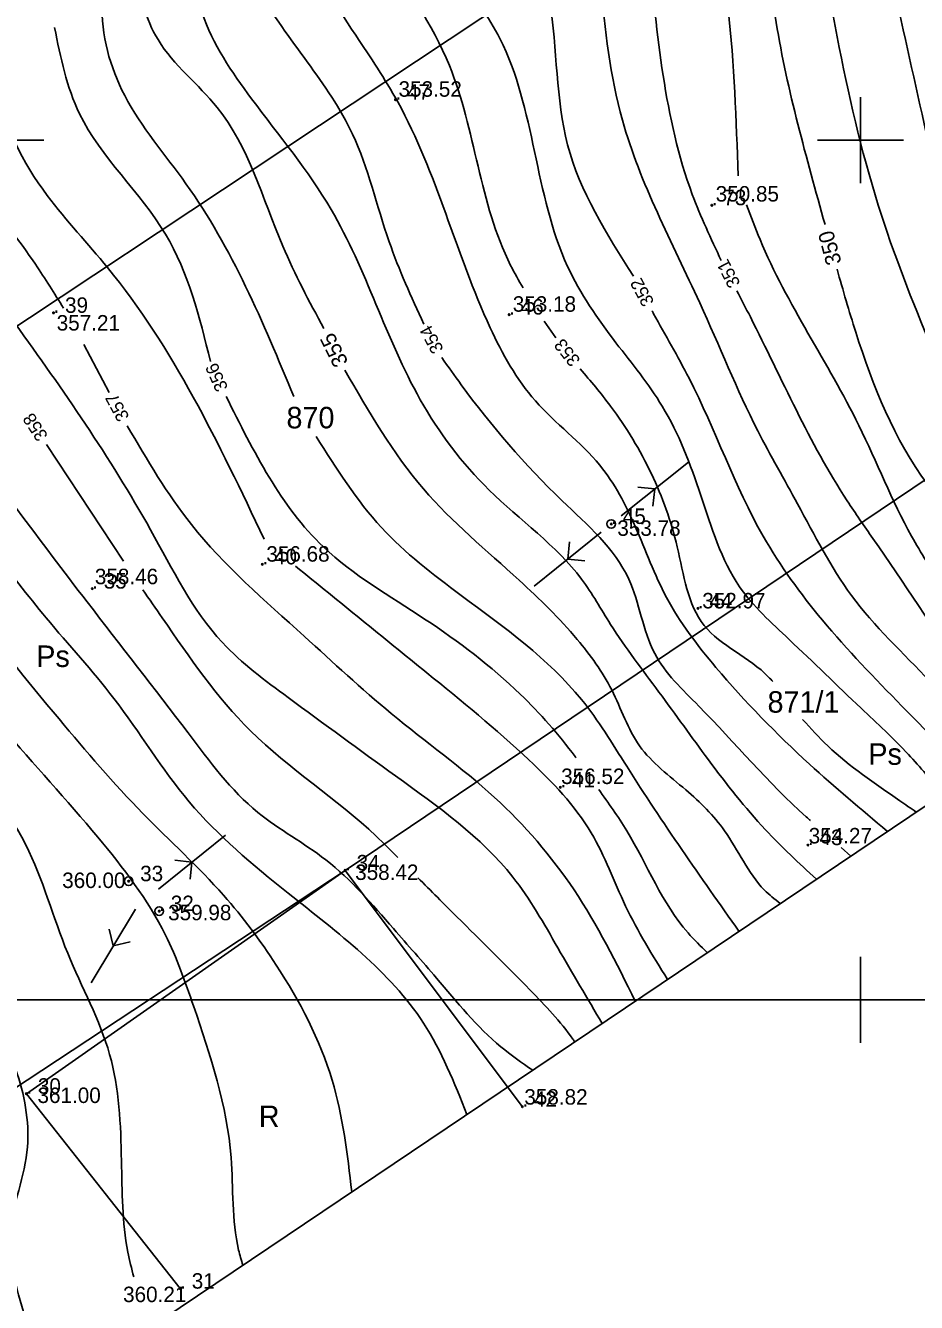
# Model space of a CAD drawing. Extents: x 4632591 to 4651936, y 5351032 to 5369988.
# Drawn here: x 4638451.4 to 4638503.3, y 5357982.4 to 5358056.7 of the extents above; entities that cross this region are included whole.
import ezdxf

# ---------------------------------------------------------------- set-up
doc = ezdxf.new("R2010")
doc.units = 0
for name, color, linetype in [('EDZPD_211', 7, 'Continuous'), ('EDZPD_219', 7, 'Continuous'), ('EKLPK_209', 7, 'Continuous'), ('EUZPU_218', 7, 'Continuous'), ('UEEPA_510', 7, 'Continuous'), ('UEETA_516', 7, 'Continuous'), ('Warstwa 40', 7, 'Continuous'), ('Warstwa 60', 7, 'Continuous'), ('Warstwa 62', 7, 'Continuous'), ('WUKPS_403', 7, 'Continuous'), ('WWRPH_811', 7, 'Continuous'), ('WWRPH_812', 7, 'Continuous'), ('WWRPH_814', 7, 'Continuous')]:
    doc.layers.add(name, color=color, linetype=linetype)

msp = doc.modelspace()

# ---------------------------------------------------------------- linework, layer by layer
at = {"layer": 'EDZPD_219'}
for p, q in [((4638429.37, 5358024.9), (4638519.216149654, 5358084.48679968)), ((4638470.0200000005, 5358007.53), (4638539.960927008, 5358054.634559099)), ((4638428.49, 5357980.16), (4638470.0200000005, 5358007.53))]:
    msp.add_line(p, q, dxfattribs=at)
at = {"layer": 'EUZPU_218'}
msp.add_lwpolyline([(4638480.33, 5357993.78), (4638470.0200000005, 5358007.53), (4638451.48, 5357994.54), (4638460.43, 5357983.2)], dxfattribs=at)
at = {"layer": 'UEEPA_510'}
for centre in [(4638485.5, 5358027.68), (4638457.43, 5358006.9), (4638459.21, 5358005.16)]:
    msp.add_circle(centre, 0.25, dxfattribs=at)
at = {"layer": 'UEETA_516'}
for p, q in [((4638486.084913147, 5358028.149442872), (4638489.984334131, 5358031.279062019)), ((4638488.034623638, 5358029.714252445), (4638487.040717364, 5358029.823102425)), ((4638488.034623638, 5358029.714252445), (4638487.925773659, 5358028.7203461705)), ((4638484.916209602, 5358027.20916163), (4638481.024273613, 5358024.070239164)), ((4638482.970241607, 5358025.639700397), (4638483.076717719, 5358026.633863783)), ((4638482.970241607, 5358025.639700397), (4638483.964404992, 5358025.533224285)), ((4638459.166196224, 5358006.441272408), (4638463.058132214, 5358009.580194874)), ((4638461.112164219, 5358008.010733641), (4638460.118000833, 5358008.117209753)), ((4638461.112164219, 5358008.010733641), (4638461.005688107, 5358007.016570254)), ((4638457.835154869, 5358005.269735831), (4638455.239730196, 5358000.996122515)), ((4638456.537442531, 5358003.132929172), (4638456.300146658, 5358004.104211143)), ((4638456.537442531, 5358003.132929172), (4638457.508724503, 5358003.370225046))]:
    msp.add_line(p, q, dxfattribs=at)
at = {"layer": 'Warstwa 40'}
msp.add_line((4638549.152447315, 5358041.831700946), (4638432.85217456, 5357963.547861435), dxfattribs=at)
at = {"layer": 'Warstwa 60'}
for p, q in [((4638500, 5358047.5), (4638500, 5358052.5)), ((4638447.5, 5358050), (4638452.5, 5358050)), ((4638497.5, 5358050), (4638502.5, 5358050)), ((4638500, 5358000), (4638500, 5358002.5)), ((4638400, 5358000), (4638516.95102771, 5358000)), ((4638500, 5357997.5), (4638500, 5358000))]:
    msp.add_line(p, q, dxfattribs=at)
at = {"layer": 'WUKPS_403'}
for centre in [(4638472.95, 5358052.36), (4638491.350000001, 5358046.22), (4638453.060000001, 5358039.96), (4638479.560000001, 5358039.86), (4638485.5, 5358027.68), (4638465.21, 5358025.33), (4638455.310000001, 5358023.92), (4638490.54, 5358022.770000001), (4638482.54, 5358012.36), (4638496.94, 5358009), (4638470.0200000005, 5358007.53), (4638457.43, 5358006.9), (4638459.21, 5358005.16), (4638451.48, 5357994.54), (4638480.33, 5357993.78), (4638460.43, 5357983.2)]:
    msp.add_circle(centre, 0.045, dxfattribs=at)
at = {"layer": 'WWRPH_811'}
for p, q in [((4638481.587630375, 5358039.48395855), (4638482.284460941, 5358038.501560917)), ((4638456.29686071, 5358035.3246872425), (4638454.820279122, 5358038.1142509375)), ((4638452.658062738, 5358032.294317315), (4638457.136709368, 5358025.5073531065)), ((4638499.435380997, 5358008.366234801), (4638498.864473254, 5358008.867941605))]:
    msp.add_line(p, q, dxfattribs=at)
for points in [[(4638488.070710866, 5358085.458534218), (4638488.086988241, 5358085.17856336), (4638486.023596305, 5358079.676184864), (4638483.459988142, 5358072.98579283), (4638485.83601522, 5358068.171211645), (4638487.649299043, 5358060.918076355), (4638490.212907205, 5358046.849494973), (4638491.893360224, 5358043.008302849)], [(4638486.784849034, 5358042.086802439), (4638482.959771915, 5358049.725738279), (4638481.896812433, 5358058.104360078), (4638480.396163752, 5358062.543779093), (4638476.456960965, 5358068.421319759), (4638476.081798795, 5358073.423482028), (4638478.20771776, 5358078.550698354), (4638479.916333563, 5358083.901363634)], [(4638475.506318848, 5358080.903647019), (4638473.017974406, 5358074.173806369), (4638469.891622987, 5358069.796914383), (4638469.829095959, 5358065.232441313), (4638472.080068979, 5358061.105657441), (4638476.081798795, 5358054.352738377), (4638479.645839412, 5358042.722711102), (4638480.367794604, 5358041.409390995)], [(4638474.591121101, 5358039.3088430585), (4638472.580285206, 5358044.0983057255), (4638470.4543662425, 5358050.351008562), (4638464.951987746, 5358058.792157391), (4638463.388812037, 5358064.106954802), (4638464.951987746, 5358068.671427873), (4638466.8277985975, 5358072.98579283), (4638467.46989627, 5358075.440872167)], [(4638447.943284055, 5358049.128498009), (4638447.819581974, 5358052.914616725), (4638447.944636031, 5358056.728765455), (4638450.195609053, 5358060.480387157), (4638451.633730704, 5358062.918941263), (4638452.356480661, 5358065.167496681)], [(4638504.751084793, 5358046.167046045), (4638504.656650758, 5358046.59938686), (4638500.779974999, 5358064.044427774), (4638500.577821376, 5358064.954119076)], [(4638453.118055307, 5358056.557453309), (4638454.572501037, 5358051.5390221), (4638459.5746633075, 5358044.535994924), (4638462.187496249, 5358037.124382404)], [(4638453.640698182, 5358040.236259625), (4638452.008892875, 5358042.78523813), (4638449.001145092, 5358046.840352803)], [(4638492.7984232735, 5358041.249282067), (4638493.589366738, 5358039.72141374), (4638499.21679929, 5358029.02929189), (4638500.71744797, 5358026.840845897), (4638505.969718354, 5358018.962440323), (4638508.533326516, 5358015.585980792), (4638509.22587246, 5358014.95639357)], [(4638506.394027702, 5358013.050227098), (4638502.405677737, 5358017.086629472), (4638497.778677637, 5358022.088791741), (4638494.339691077, 5358026.965899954), (4638490.025326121, 5358036.157373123), (4638487.961934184, 5358039.908994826), (4638487.866653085, 5358040.084426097)], [(4638497.095087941, 5358010.42285597), (4638496.8407722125, 5358010.64634555), (4638490.588069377, 5358017.086629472), (4638488.024461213, 5358020.150453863), (4638486.5238125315, 5358024.464818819), (4638482.647136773, 5358029.02929189), (4638476.769596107, 5358035.782210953), (4638475.645039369, 5358037.354334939)], [(4638483.692122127, 5358036.703176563), (4638485.4608530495, 5358034.531670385), (4638487.836880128, 5358030.592467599), (4638489.337528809, 5358026.34062967), (4638490.900704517, 5358021.776156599), (4638494.65232622, 5358018.7748592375), (4638494.888121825, 5358018.518959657)], [(4638463.099828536, 5358035.096232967), (4638468.766136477, 5358026.34062967), (4638474.643677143, 5358022.15131877), (4638480.208582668, 5358017.774426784), (4638483.397461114, 5358014.147859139), (4638483.450684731, 5358014.07613187)], [(4638486.893629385, 5357999.924152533), (4638483.334934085, 5358006.394507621), (4638478.707933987, 5358011.771832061), (4638472.705339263, 5358016.648940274), (4638467.640649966, 5358021.150886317), (4638461.075311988, 5358027.653697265), (4638457.347085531, 5358033.396699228)], [(4638477.10710023, 5357993.336660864), (4638474.581150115, 5357998.641156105), (4638466.702744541, 5358006.206926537), (4638460.950257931, 5358011.5217239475), (4638456.573365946, 5358017.52431867), (4638452.634163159, 5358022.213845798), (4638446.6097368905, 5358030.42932701)], [(4638435.92321611, 5358029.499414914), (4638436.439662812, 5358028.716656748), (4638439.315906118, 5358021.8386836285), (4638442.879946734, 5358015.085764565), (4638447.757054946, 5358006.957250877), (4638448.820014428, 5358001.142237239), (4638450.945933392, 5357995.702385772), (4638451.508676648, 5357991.137912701), (4638450.508244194, 5357986.073223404), (4638451.571203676, 5357980.88348005), (4638452.294395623, 5357976.634775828)], [(4638458.246488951, 5358023.857936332), (4638459.387082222, 5358022.213845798), (4638464.514298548, 5358015.64850782), (4638471.829960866, 5358009.52085904), (4638473.076593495, 5358008.274226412)], [(4638496.63143432, 5358016.313603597), (4638498.091312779, 5358014.773129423), (4638502.280623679, 5358011.584250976), (4638503.2319100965, 5358010.921747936)], [(4638484.768335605, 5358012.239052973), (4638486.398758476, 5358009.833494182), (4638489.962799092, 5358003.893426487), (4638491.085819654, 5358002.745992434)], [(4638474.248975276, 5358007.10184463), (4638476.519487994, 5358004.831331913), (4638480.771325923, 5358000.579493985), (4638483.272407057, 5357997.703250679), (4638483.374698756, 5357997.555496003)]]:
    msp.add_spline(points, degree=3, dxfattribs=at)
at = {"layer": 'WWRPH_812'}
for points in [[(4638490.057391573, 5358090.794768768), (4638490.337961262, 5358086.866793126), (4638489.275001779, 5358082.052211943), (4638488.086988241, 5358076.737414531), (4638488.5872044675, 5358071.610198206), (4638490.275434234, 5358066.920671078), (4638492.88174233, 5358047.928997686)], [(4638507.894152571, 5358014.05998857), (4638504.031380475, 5358018.524751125), (4638499.466907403, 5358023.526913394), (4638496.340555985, 5358028.841710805), (4638494.027055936, 5358033.093548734), (4638490.650596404, 5358040.534265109), (4638486.148650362, 5358051.163859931), (4638484.898109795, 5358059.167319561), (4638483.835150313, 5358064.607171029), (4638480.833852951, 5358069.609333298), (4638480.708798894, 5358073.73611717), (4638481.709231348, 5358077.550265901), (4638483.022298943, 5358083.115171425), (4638483.397461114, 5358087.241955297)], [(4638477.318384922, 5358082.135402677), (4638475.706636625, 5358077.300157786), (4638474.205987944, 5358072.673157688), (4638472.955447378, 5358066.8581440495), (4638476.644542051, 5358059.542481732), (4638479.020569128, 5358055.915914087), (4638482.959771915, 5358042.660184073), (4638485.773488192, 5358038.22076506), (4638488.462150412, 5358034.531670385), (4638490.713123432, 5358029.341927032), (4638492.964096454, 5358024.02712962), (4638495.840339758, 5358020.963305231), (4638500.029650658, 5358016.961575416), (4638502.780839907, 5358014.272913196), (4638504.781510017, 5358011.964811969)], [(4638501.564705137, 5358009.799521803), (4638497.028353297, 5358013.710169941), (4638491.58850183, 5358019.337602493), (4638488.712258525, 5358023.4018593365), (4638486.898974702, 5358027.5286432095), (4638484.835582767, 5358031.092683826), (4638481.083961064, 5358034.844305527), (4638478.457825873, 5358039.096143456), (4638473.080501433, 5358052.226819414), (4638470.641947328, 5358056.103495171), (4638467.140433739, 5358062.231143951), (4638466.265055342, 5358066.8581440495), (4638467.703176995, 5358070.047022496), (4638469.704041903, 5358073.423482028), (4638470.829528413, 5358076.987522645), (4638470.968068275, 5358077.818761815)], [(4638510.7567898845, 5358026.726471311), (4638507.345312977, 5358031.467845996), (4638504.15643453, 5358037.908129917), (4638501.030083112, 5358046.224224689), (4638496.90329924, 5358065.982765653), (4638495.715285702, 5358072.23546849), (4638494.777380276, 5358076.737414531), (4638494.743845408, 5358076.974587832)], [(4638466.0976399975, 5358074.508078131), (4638464.576825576, 5358070.047022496), (4638461.763109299, 5358064.857279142), (4638461.700582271, 5358057.416562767), (4638464.576825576, 5358052.414400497), (4638469.203825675, 5358045.974116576), (4638474.39356903, 5358034.906832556), (4638478.395298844, 5358029.654562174), (4638483.772623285, 5358024.464818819), (4638485.46085305, 5358021.8386836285), (4638488.274569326, 5358017.899480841), (4638491.150812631, 5358013.960278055), (4638494.464745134, 5358009.896021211), (4638497.431606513, 5358007.017457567)], [(4638467.037657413, 5358035.0888308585), (4638460.762676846, 5358047.474765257), (4638457.198636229, 5358052.601981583), (4638455.885568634, 5358057.979306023), (4638457.261163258, 5358062.731360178), (4638459.699717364, 5358066.48298188), (4638461.200366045, 5358069.046590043), (4638462.135595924, 5358071.814870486)], [(4638455.511596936, 5358067.312193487), (4638453.196906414, 5358062.856414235), (4638450.883406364, 5358057.916778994), (4638449.945500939, 5358053.227251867), (4638452.696690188, 5358046.786967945), (4638456.198203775, 5358042.597657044), (4638465.308231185, 5358026.795056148)], [(4638484.967158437, 5357998.627409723), (4638482.3970286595, 5358003.01804809), (4638479.7708934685, 5358007.144831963), (4638472.955447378, 5358013.022372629), (4638466.702744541, 5358017.5868457), (4638462.88859581, 5358020.775724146), (4638458.69928491, 5358027.341062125), (4638450.820879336, 5358039.34625157), (4638447.069257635, 5358044.348413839), (4638445.130919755, 5358047.287184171), (4638445.130919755, 5358052.414400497), (4638446.381460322, 5358056.978873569), (4638448.507379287, 5358060.855549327), (4638450.258136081, 5358063.606738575), (4638450.349313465, 5358063.803120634)], [(4638470.403249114, 5357988.8241761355), (4638469.266352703, 5357995.327223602), (4638466.014947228, 5358002.017615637), (4638462.951122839, 5358006.081872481), (4638458.261595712, 5358010.833926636), (4638453.3844874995, 5358016.336305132), (4638442.942473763, 5358030.592467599), (4638440.941608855, 5358034.093981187), (4638438.06536555, 5358037.970656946), (4638435.751865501, 5358040.909427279), (4638435.37670333, 5358044.223359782), (4638436.627243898, 5358049.725738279), (4638438.002838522, 5358053.664941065), (4638438.3027634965, 5358055.614453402)], [(4638434.334201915, 5358052.916815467), (4638432.375405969, 5358047.349711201), (4638430.687176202, 5358042.660184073), (4638431.750135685, 5358038.283292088), (4638434.313743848, 5358033.906400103), (4638438.06536555, 5358029.592035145), (4638441.566879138, 5358022.088791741), (4638451.44614962, 5358009.020642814), (4638453.884703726, 5358002.7054129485), (4638456.323257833, 5357996.827872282), (4638457.0110551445, 5357990.637696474), (4638457.386217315, 5357985.322899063), (4638457.723256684, 5357983.885001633)], [(4638493.368167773, 5358046.246809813), (4638494.152109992, 5358044.223359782), (4638499.904596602, 5358033.406183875), (4638502.968420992, 5358026.965899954), (4638503.813713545, 5358025.533435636)], [(4638446.951934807, 5358033.890704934), (4638455.010190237, 5358023.151751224), (4638460.887730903, 5358015.523453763), (4638464.951987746, 5358010.896453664), (4638468.8911905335, 5358008.145264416), (4638472.83039332, 5358004.143534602), (4638475.331474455, 5358001.267291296), (4638479.083096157, 5357997.265561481), (4638480.929096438, 5357995.909316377)], [(4638492.925971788, 5358003.984632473), (4638486.398758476, 5358013.5851158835), (4638483.772623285, 5358017.461791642), (4638476.769596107, 5358023.526913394), (4638472.142596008, 5358027.466116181), (4638468.338275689, 5358032.766433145)], [(4638467.135539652, 5358025.227871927), (4638474.768731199, 5358019.024967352), (4638480.708798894, 5358013.960278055), (4638484.335366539, 5358009.708440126), (4638486.336231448, 5358005.456602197), (4638488.769860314, 5358001.187077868)]]:
    msp.add_spline(points, degree=3, dxfattribs=at)
at = {"layer": 'WWRPH_814'}
for points in [[(4638497.93603946, 5358045.092001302), (4638495.090015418, 5358056.853819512), (4638493.08915051, 5358068.796481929), (4638491.150812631, 5358076.049617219), (4638491.838609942, 5358082.177265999), (4638492.901569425, 5358086.554157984), (4638493.2142045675, 5358090.243252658), (4638492.843315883, 5358092.688506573)], [(4638464.784079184, 5358073.615182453), (4638462.2007984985, 5358067.983630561), (4638459.324555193, 5358063.294103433), (4638458.136541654, 5358059.855116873), (4638459.136974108, 5358055.853387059), (4638462.575960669, 5358051.914184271), (4638466.390109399, 5358043.848197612), (4638468.779879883, 5358039.050299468)], [(4638506.179661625, 5358027.277617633), (4638503.906326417, 5358029.967197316), (4638499.717015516, 5358038.846035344), (4638498.633209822, 5358042.492694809)], [(4638470.002639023, 5358036.63384721), (4638474.581150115, 5358029.717089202), (4638480.146055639, 5358024.4022917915), (4638483.52251517, 5358020.963305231), (4638485.523380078, 5358018.024534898), (4638487.149082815, 5358014.773129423), (4638489.837745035, 5358012.209521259), (4638492.088718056, 5358009.833494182), (4638494.402218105, 5358006.394507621), (4638495.320220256, 5358005.596244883)], [(4638440.979502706, 5358028.942549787), (4638445.005865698, 5358022.276372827), (4638450.070554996, 5358015.836088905), (4638455.63546052, 5358009.458332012), (4638459.5746633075, 5358003.7683724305), (4638461.200366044, 5357999.641588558), (4638463.388812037, 5357990.825277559), (4638463.826501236, 5357985.447953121), (4638464.072388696, 5357984.562758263)]]:
    msp.add_spline(points, degree=3, dxfattribs=at)

# ---------------------------------------------------------------- texts
at = {"layer": 'EDZPD_211'}
for s, p in [('870', (4638466.608953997, 5358033.242050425)), ('871/1', (4638494.58979919, 5358016.703651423))]:
    msp.add_text(s, height=1.25, dxfattribs=at).set_placement(p)
at = {"layer": 'EKLPK_209'}
for s, p in [('Ps', (4638452.055788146, 5358019.361050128)), ('Ps', (4638500.4517081, 5358013.671090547)), ('R', (4638464.998883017, 5357992.599481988))]:
    msp.add_text(s, height=1.25, dxfattribs=at).set_placement(p)
at = {"layer": 'Warstwa 62'}
for s, p in [('. 47', (4638472.95, 5358052.36)), ('. 73', (4638491.350000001, 5358046.22)), ('. 39', (4638453.0600000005, 5358039.96)), ('. 46', (4638479.5600000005, 5358039.86)), ('. 45', (4638485.5, 5358027.68)), ('. 40', (4638465.21, 5358025.33)), ('. 35', (4638455.3100000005, 5358023.92)), ('. 44', (4638490.54, 5358022.7700000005)), ('. 41', (4638482.54, 5358012.36)), ('. 43', (4638496.94, 5358009)), ('. 34', (4638470.0200000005, 5358007.53)), ('. 33', (4638457.43, 5358006.9)), ('. 32', (4638459.21, 5358005.16)), ('. 30', (4638451.48, 5357994.54)), ('. 42', (4638480.33, 5357993.78)), ('. 31', (4638460.43, 5357983.2))]:
    msp.add_text(s, height=0.9, dxfattribs=at).set_placement(p)
at = {"layer": 'WUKPS_403'}
for s, p in [('353.52', (4638473.127396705, 5358052.531638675)), ('350.85', (4638491.572870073, 5358046.435253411)), ('353.18', (4638479.7708934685, 5358040.0262330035)), ('357.21', (4638453.243801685, 5358038.932010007)), ('353.78', (4638485.851646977, 5358026.989347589)), ('356.68', (4638465.436572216, 5358025.488698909)), ('358.46', (4638455.463511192, 5358024.175631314)), ('352.97', (4638490.791282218, 5358022.768773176)), ('356.52', (4638482.584609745, 5358012.553419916)), ('354.27', (4638496.981458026, 5358009.098801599)), ('358.42', (4638470.602867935, 5358006.972882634)), ('360.00', (4638453.564252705, 5358006.503929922)), ('359.98', (4638459.723165, 5358004.628119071)), ('361.00', (4638452.126131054, 5357993.9985242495)), ('358.82', (4638480.443059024, 5357993.904733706)), ('360.21', (4638457.104845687, 5357982.415392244))]:
    msp.add_text(s, height=0.9, dxfattribs=at).set_placement(p)
at = {"layer": 'WWRPH_811'}
for s, height, rotation, p in [('351', 0.75, 117.29475230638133, (4638493.028223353, 5358041.6627775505)), ('352', 0.75, 118.39396925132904, (4638488.017156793, 5358040.5920624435)), ('354', 0.75, 118.20038730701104, (4638475.770155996, 5358037.844606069)), ('353', 0.75, 128.2816196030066, (4638483.740548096, 5358037.218519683)), ('356', 0.7499999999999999, 114.13696085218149, (4638463.227707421, 5358035.590425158)), ('357', 0.75, 118.54251813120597, (4638457.492067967, 5358033.902360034)), ('358', 0.75, 123.31538640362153, (4638452.765486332, 5358032.813669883))]:
    msp.add_text(s, height=height, rotation=rotation, dxfattribs=at).set_placement(p)
at = {"layer": 'WWRPH_814'}
for s, height, rotation, p in [('350', 0.9, 105.02446503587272, (4638498.901343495, 5358042.876471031)), ('355', 0.8999999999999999, 116.77782271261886, (4638470.224044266, 5358037.092260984))]:
    msp.add_text(s, height=height, rotation=rotation, dxfattribs=at).set_placement(p)

doc.saveas('drawing.dxf')
